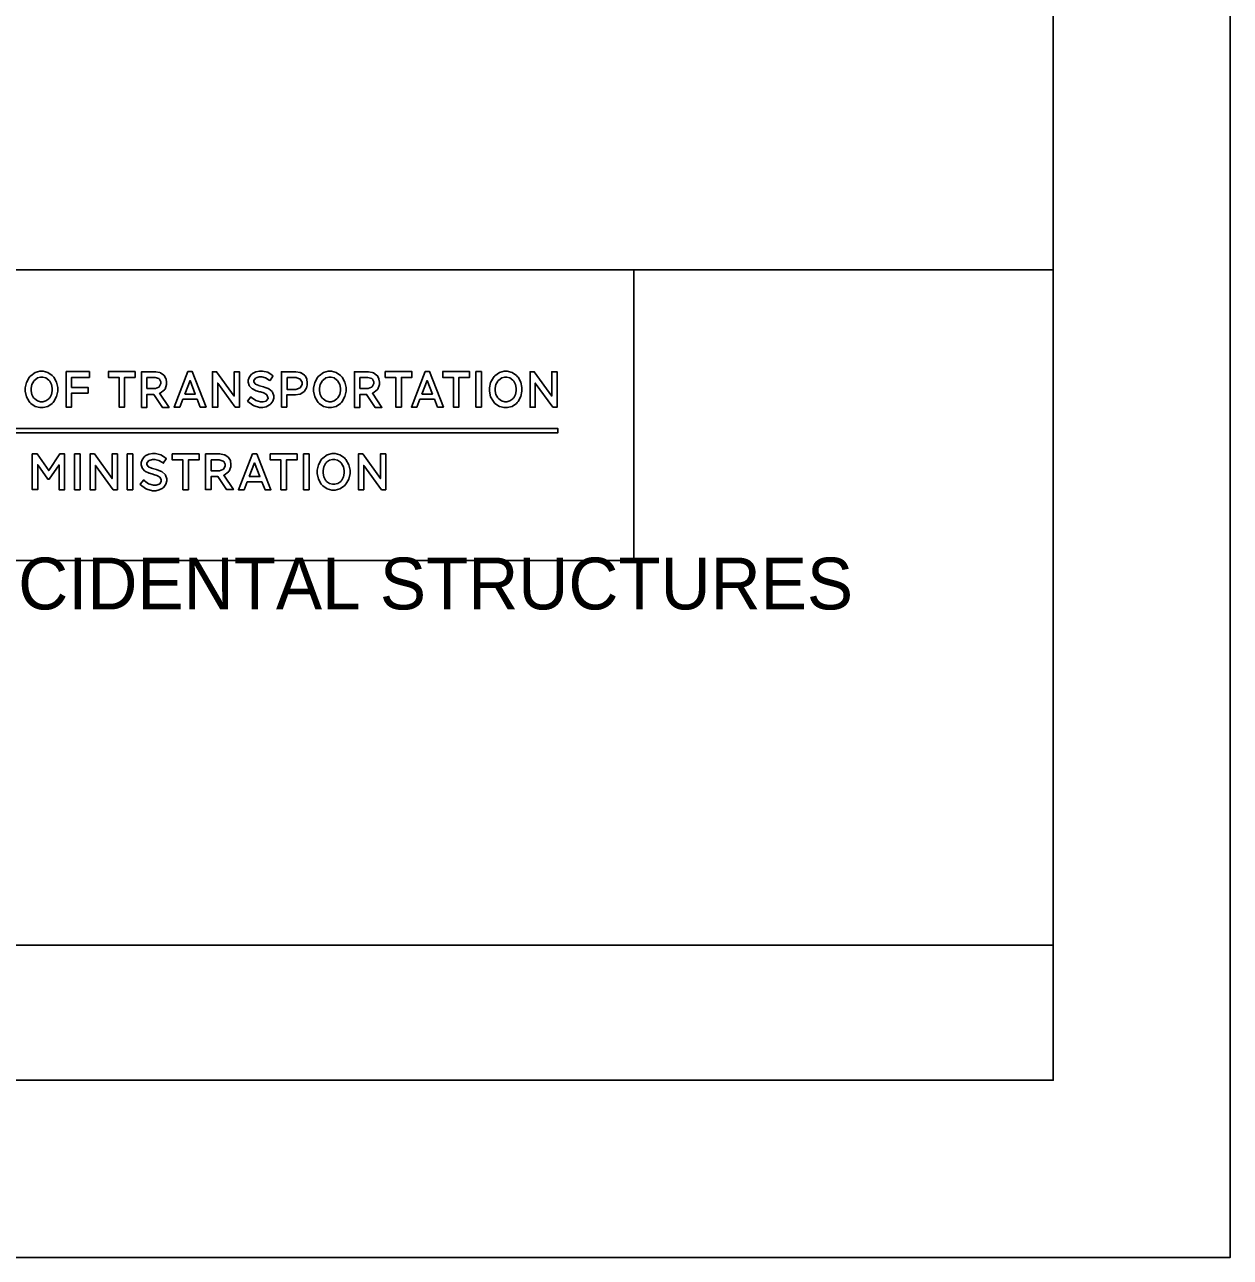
# Model space of a CAD drawing. Extents: x 12.2 to 54.5, y -7.8 to 16.1.
# Drawn here: x 52.376 to 54.534, y -7.78 to -5.573 of the extents above; entities that cross this region are included whole.
import ezdxf

# ---------------------------------------------------------------- set-up
doc = ezdxf.new("R2010")
doc.units = 0
for name, color, linetype in [('BORD-LINE', 7, 'Continuous'), ('MSHA-LOGO', 7, 'Continuous'), ('TTLB-TEXT', 7, 'Continuous'), ('USER-BORD', 7, 'Continuous'), ('USER-LINE', 7, 'Continuous')]:
    doc.layers.add(name, color=color, linetype=linetype)

msp = doc.modelspace()

# ---------------------------------------------------------------- linework, layer by layer
at = {"layer": 'BORD-LINE'}
for p, q in [((54.2173, -6.0121), (49.7444, -6.0121)), ((49.7444, -7.2211), (54.2173, -7.2211))]:
    msp.add_line(p, q, dxfattribs=at)
msp.add_lwpolyline([(46.8431, 2.8902), (54.2173, 2.8902), (54.2173, -7.4629), (46.8431, -7.4629)], close=True, dxfattribs=at)
at = {"layer": 'MSHA-LOGO'}
for points in [[(52.3857, -6.2033), (52.3871, -6.2018), (52.395, -6.1962), (52.4035, -6.1938), (52.4063, -6.1938), (52.4091, -6.1938), (52.4176, -6.1961), (52.4255, -6.2014), (52.4269, -6.203), (52.4283, -6.2046), (52.4333, -6.2135), (52.4354, -6.2231), (52.4354, -6.2264), (52.4354, -6.2296), (52.4333, -6.2392), (52.4283, -6.2482), (52.4269, -6.2497), (52.4255, -6.2513), (52.4176, -6.2567), (52.4091, -6.2589), (52.4063, -6.2589), (52.4035, -6.2589), (52.395, -6.2567), (52.3871, -6.2513), (52.3857, -6.2497), (52.3843, -6.2482), (52.3793, -6.2393), (52.3772, -6.2296), (52.3772, -6.2264), (52.3772, -6.2232), (52.3793, -6.2137), (52.3843, -6.2049)], [(52.4502, -6.1945), (52.4921, -6.1945), (52.4921, -6.2047), (52.46, -6.2047), (52.46, -6.2228), (52.4898, -6.2228), (52.4898, -6.233), (52.46, -6.233), (52.46, -6.258), (52.4502, -6.258)], [(52.5258, -6.1945), (52.5739, -6.1945), (52.5739, -6.2047), (52.5549, -6.2047), (52.5549, -6.258), (52.5451, -6.258), (52.5451, -6.2047), (52.5261, -6.2047), (52.5261, -6.1945)], [(52.5853, -6.2583), (52.5853, -6.1948), (52.6076, -6.1948), (52.6104, -6.1948), (52.6179, -6.1962), (52.6187, -6.1964), (52.6194, -6.1967), (52.6252, -6.2006), (52.6256, -6.201), (52.626, -6.2015), (52.6289, -6.2067), (52.6292, -6.2073), (52.6294, -6.2079), (52.6302, -6.2131), (52.6302, -6.2149), (52.6302, -6.2177), (52.6274, -6.2256), (52.6269, -6.2264), (52.6263, -6.2272), (52.6187, -6.233), (52.6177, -6.2333), (52.6347, -6.2586), (52.6226, -6.2586), (52.6072, -6.2353), (52.5951, -6.2353), (52.5951, -6.2586), (52.5853, -6.2586)], [(52.6685, -6.1945), (52.676, -6.1945), (52.7008, -6.258), (52.6904, -6.258), (52.6848, -6.2438), (52.6593, -6.2438), (52.6537, -6.258), (52.6436, -6.258)], [(52.7532, -6.2583), (52.7218, -6.2149), (52.7218, -6.2583), (52.7123, -6.2583), (52.7123, -6.1948), (52.7198, -6.1948), (52.7512, -6.2382), (52.7512, -6.1948), (52.7607, -6.1948), (52.7607, -6.2583)], [(52.8095, -6.2359), (52.8092, -6.2356), (52.8051, -6.2329), (52.8046, -6.2326), (52.8041, -6.2325), (52.7984, -6.2308), (52.7977, -6.2307), (52.7971, -6.2305), (52.7908, -6.2286), (52.7902, -6.2284), (52.7895, -6.2281), (52.7838, -6.2254), (52.7833, -6.2251), (52.7828, -6.2247), (52.7787, -6.2204), (52.7784, -6.2198), (52.7781, -6.2192), (52.7765, -6.2135), (52.7765, -6.2116), (52.7765, -6.2098), (52.7779, -6.2047), (52.7816, -6.1996), (52.7827, -6.1988), (52.7837, -6.1978), (52.7898, -6.1947), (52.7965, -6.1935), (52.7987, -6.1935), (52.8018, -6.1935), (52.8112, -6.1957), (52.8193, -6.2011), (52.8206, -6.2027), (52.8154, -6.2106), (52.8141, -6.2095), (52.8075, -6.2057), (52.8006, -6.204), (52.7984, -6.204), (52.7962, -6.204), (52.7904, -6.2056), (52.7899, -6.206), (52.7893, -6.2063), (52.7866, -6.2103), (52.7866, -6.2116), (52.7866, -6.2128), (52.7888, -6.2162), (52.7892, -6.2165), (52.7896, -6.2168), (52.7951, -6.2193), (52.7957, -6.2195), (52.7964, -6.2196), (52.8035, -6.2215), (52.8043, -6.2218), (52.805, -6.222), (52.8121, -6.2247), (52.8128, -6.2251), (52.8134, -6.2254), (52.8189, -6.23), (52.8193, -6.2307), (52.8197, -6.2313), (52.8219, -6.2377), (52.8219, -6.2399), (52.8219, -6.2417), (52.8204, -6.2473), (52.8168, -6.2524), (52.8157, -6.2534), (52.8146, -6.2542), (52.8086, -6.2573), (52.8024, -6.2586), (52.8003, -6.2586), (52.7967, -6.2586), (52.7871, -6.2559), (52.7859, -6.2553), (52.7848, -6.2547), (52.7758, -6.2479), (52.7751, -6.2471), (52.781, -6.2395), (52.7823, -6.241), (52.7899, -6.2464), (52.7982, -6.2488), (52.801, -6.2488), (52.803, -6.2488), (52.8084, -6.2471), (52.8088, -6.2468), (52.8093, -6.2464), (52.8118, -6.2425), (52.8118, -6.2412), (52.8117, -6.2406), (52.8098, -6.2362)], [(52.8357, -6.2583), (52.8357, -6.1948), (52.8586, -6.1948), (52.8615, -6.1948), (52.8695, -6.1962), (52.8704, -6.1964), (52.8712, -6.1968), (52.8771, -6.2009), (52.8776, -6.2014), (52.878, -6.2019), (52.881, -6.2074), (52.8812, -6.208), (52.8813, -6.2085), (52.8821, -6.2138), (52.8821, -6.2155), (52.8821, -6.2174), (52.8811, -6.2225), (52.8808, -6.2231), (52.8806, -6.2236), (52.8773, -6.2292), (52.8769, -6.2297), (52.8765, -6.2302), (52.8702, -6.2343), (52.8694, -6.2346), (52.8686, -6.2349), (52.8608, -6.2362), (52.8583, -6.2362), (52.8452, -6.2362), (52.8452, -6.258), (52.8357, -6.258)], [(52.9018, -6.2033), (52.9032, -6.2018), (52.9111, -6.1962), (52.9196, -6.1938), (52.9224, -6.1938), (52.9252, -6.1938), (52.9337, -6.1961), (52.9416, -6.2014), (52.943, -6.203), (52.9444, -6.2046), (52.9493, -6.2135), (52.9515, -6.2231), (52.9515, -6.2264), (52.9515, -6.2296), (52.9493, -6.2392), (52.9444, -6.2482), (52.943, -6.2497), (52.9416, -6.2513), (52.9337, -6.2567), (52.9252, -6.2589), (52.9224, -6.2589), (52.9196, -6.2589), (52.9111, -6.2567), (52.9032, -6.2513), (52.9018, -6.2497), (52.9004, -6.2482), (52.8954, -6.2393), (52.8933, -6.2296), (52.8933, -6.2264), (52.8933, -6.2241), (52.8956, -6.2137), (52.9004, -6.2049)], [(52.9663, -6.2583), (52.9663, -6.1948), (52.9885, -6.1948), (52.9913, -6.1948), (52.9988, -6.1962), (52.9996, -6.1964), (53.0004, -6.1967), (53.0061, -6.2006), (53.0065, -6.201), (53.0069, -6.2015), (53.0098, -6.2067), (53.0101, -6.2073), (53.0102, -6.2079), (53.0111, -6.2131), (53.0111, -6.2149), (53.0111, -6.2177), (53.0084, -6.2256), (53.0078, -6.2264), (53.0072, -6.2272), (52.9996, -6.233), (52.9986, -6.2333), (53.0157, -6.2586), (53.0035, -6.2586), (52.9882, -6.2353), (52.9761, -6.2353), (52.9761, -6.2586), (52.9663, -6.2586)], [(53.0212, -6.1945), (53.0693, -6.1945), (53.0693, -6.2047), (53.0504, -6.2047), (53.0504, -6.258), (53.0405, -6.258), (53.0405, -6.2047), (53.0215, -6.2047), (53.0215, -6.1945)], [(53.0932, -6.1945), (53.1008, -6.1945), (53.1256, -6.258), (53.1152, -6.258), (53.1096, -6.2438), (53.0837, -6.2438), (53.0782, -6.258), (53.0684, -6.258)], [(53.1243, -6.1945), (53.1724, -6.1945), (53.1724, -6.2047), (53.1534, -6.2047), (53.1534, -6.258), (53.1436, -6.258), (53.1436, -6.2047), (53.1246, -6.2047), (53.1246, -6.1945)], [(53.1839, -6.1945), (53.1937, -6.1945), (53.1937, -6.258), (53.1839, -6.258)], [(53.2166, -6.2033), (53.218, -6.2018), (53.2259, -6.1962), (53.2344, -6.1938), (53.2372, -6.1938), (53.24, -6.1938), (53.2485, -6.1961), (53.2564, -6.2014), (53.2578, -6.203), (53.2592, -6.2046), (53.2642, -6.2135), (53.2663, -6.2231), (53.2663, -6.2264), (53.2663, -6.2296), (53.2642, -6.2392), (53.2592, -6.2482), (53.2578, -6.2497), (53.2564, -6.2513), (53.2485, -6.2567), (53.24, -6.2589), (53.2372, -6.2589), (53.2344, -6.2589), (53.2259, -6.2567), (53.218, -6.2513), (53.2166, -6.2497), (53.2152, -6.2482), (53.2102, -6.2393), (53.2081, -6.2296), (53.2081, -6.2264), (53.2081, -6.2232), (53.2101, -6.2137), (53.2151, -6.2049)], [(53.3216, -6.2583), (53.2902, -6.2149), (53.2902, -6.2583), (53.2807, -6.2583), (53.2807, -6.1948), (53.2883, -6.1948), (53.3197, -6.2382), (53.3197, -6.1948), (53.3292, -6.1948), (53.3292, -6.2583)], [(52.3932, -6.2422), (52.3941, -6.2432), (52.3993, -6.2469), (52.4048, -6.2484), (52.4067, -6.2484), (52.4085, -6.2484), (52.414, -6.2469), (52.4192, -6.2432), (52.4201, -6.2422), (52.421, -6.2412), (52.4242, -6.2352), (52.4256, -6.2286), (52.4256, -6.2264), (52.4256, -6.2241), (52.4242, -6.2175), (52.421, -6.2116), (52.4201, -6.2106), (52.4192, -6.2095), (52.414, -6.2058), (52.4085, -6.2043), (52.4067, -6.2043), (52.4048, -6.2043), (52.3993, -6.2058), (52.3941, -6.2095), (52.3932, -6.2106), (52.3923, -6.2116), (52.3891, -6.2175), (52.3877, -6.2241), (52.3877, -6.2264), (52.3877, -6.2286), (52.389, -6.2352), (52.3922, -6.2412)], [(52.5951, -6.205), (52.5951, -6.2244), (52.6079, -6.2244), (52.6101, -6.2244), (52.6162, -6.2222), (52.6167, -6.2218), (52.6172, -6.2214), (52.62, -6.216), (52.62, -6.2142), (52.62, -6.2125), (52.6175, -6.2077), (52.6171, -6.2073), (52.6166, -6.2069), (52.6098, -6.205), (52.6076, -6.205)], [(52.6629, -6.2346), (52.6815, -6.2346), (52.6721, -6.2106)], [(52.8458, -6.205), (52.8458, -6.2264), (52.8589, -6.2264), (52.8615, -6.2264), (52.8692, -6.2236), (52.8726, -6.2175), (52.8726, -6.2155), (52.8726, -6.2136), (52.8694, -6.2077), (52.862, -6.205), (52.8596, -6.205)], [(52.9093, -6.2422), (52.9102, -6.2432), (52.9154, -6.2469), (52.9209, -6.2484), (52.9227, -6.2484), (52.9245, -6.2484), (52.93, -6.2469), (52.9352, -6.2432), (52.9361, -6.2422), (52.937, -6.2412), (52.9403, -6.2352), (52.9417, -6.2286), (52.9417, -6.2264), (52.9417, -6.2241), (52.9403, -6.2175), (52.937, -6.2116), (52.9361, -6.2106), (52.9352, -6.2095), (52.93, -6.2058), (52.9245, -6.2043), (52.9227, -6.2043), (52.9209, -6.2043), (52.9155, -6.2058), (52.9103, -6.2095), (52.9093, -6.2106), (52.9084, -6.2116), (52.9052, -6.2175), (52.9037, -6.2241), (52.9037, -6.2264), (52.9037, -6.2286), (52.905, -6.2352), (52.9083, -6.2412)], [(52.9761, -6.205), (52.9761, -6.2244), (52.9888, -6.2244), (52.991, -6.2244), (52.9971, -6.2222), (52.9977, -6.2218), (52.9981, -6.2214), (53.0009, -6.216), (53.0009, -6.2142), (53.0009, -6.2125), (52.9985, -6.2077), (52.998, -6.2073), (52.9975, -6.2069), (52.9907, -6.205), (52.9885, -6.205)], [(53.0873, -6.2346), (53.106, -6.2346), (53.0965, -6.2106)], [(53.2238, -6.2422), (53.2247, -6.2432), (53.2299, -6.2469), (53.2354, -6.2484), (53.2372, -6.2484), (53.239, -6.2484), (53.2445, -6.2469), (53.2497, -6.2432), (53.2506, -6.2422), (53.2515, -6.2412), (53.2548, -6.2352), (53.2562, -6.2286), (53.2562, -6.2264), (53.2562, -6.2241), (53.2548, -6.2175), (53.2515, -6.2116), (53.2506, -6.2106), (53.2497, -6.2095), (53.2445, -6.2058), (53.239, -6.2043), (53.2372, -6.2043), (53.2354, -6.2043), (53.23, -6.2058), (53.2248, -6.2095), (53.2238, -6.2106), (53.2229, -6.2116), (53.2197, -6.2175), (53.2182, -6.2241), (53.2182, -6.2264), (53.2182, -6.2286), (53.2197, -6.2352), (53.2229, -6.2412)], [(51.2136, -6.2962), (53.3302, -6.2962), (53.3302, -6.3041), (51.2136, -6.3041)], [(52.3898, -6.3418), (52.3987, -6.3418), (52.4192, -6.3716), (52.439, -6.3418), (52.4476, -6.3418), (52.4476, -6.406), (52.4377, -6.406), (52.4377, -6.3614), (52.4201, -6.3867), (52.4176, -6.3867), (52.3997, -6.361), (52.3997, -6.4057), (52.3898, -6.4057)], [(52.4655, -6.3418), (52.4754, -6.3418), (52.4754, -6.406), (52.4655, -6.406)], [(52.5345, -6.406), (52.5029, -6.3623), (52.5029, -6.406), (52.4933, -6.406), (52.4933, -6.3418), (52.501, -6.3418), (52.5326, -6.3858), (52.5326, -6.3418), (52.5422, -6.3418), (52.5422, -6.406)], [(52.5597, -6.3418), (52.5696, -6.3418), (52.5696, -6.406), (52.5597, -6.406)], [(52.6185, -6.3838), (52.6182, -6.3835), (52.614, -6.3809), (52.6134, -6.3806), (52.6129, -6.3805), (52.607, -6.3785), (52.6064, -6.3784), (52.6057, -6.3782), (52.5994, -6.3764), (52.5987, -6.3761), (52.5981, -6.3759), (52.5922, -6.3732), (52.5917, -6.3729), (52.5911, -6.3726), (52.5869, -6.368), (52.5866, -6.3675), (52.5863, -6.3669), (52.5847, -6.361), (52.5847, -6.3591), (52.5847, -6.3574), (52.5863, -6.3521), (52.59, -6.3471), (52.5911, -6.3463), (52.5921, -6.3454), (52.5982, -6.3424), (52.6051, -6.3411), (52.6074, -6.3411), (52.6105, -6.3411), (52.6201, -6.3435), (52.6284, -6.3489), (52.6297, -6.3504), (52.6243, -6.3585), (52.6231, -6.3573), (52.6164, -6.3534), (52.6094, -6.3517), (52.607, -6.3517), (52.6049, -6.3517), (52.599, -6.3533), (52.5984, -6.3537), (52.5978, -6.354), (52.5949, -6.3581), (52.5949, -6.3594), (52.5949, -6.3607), (52.5971, -6.3642), (52.5975, -6.3646), (52.5979, -6.3649), (52.6034, -6.3673), (52.6042, -6.3675), (52.6049, -6.3676), (52.612, -6.3698), (52.6128, -6.37), (52.6136, -6.3703), (52.6208, -6.373), (52.6214, -6.3732), (52.622, -6.3736), (52.6276, -6.3784), (52.6281, -6.379), (52.6285, -6.3797), (52.6307, -6.3862), (52.6307, -6.3883), (52.6307, -6.3902), (52.629, -6.396), (52.6253, -6.4013), (52.6243, -6.4021), (52.6232, -6.403), (52.6172, -6.4062), (52.6108, -6.4076), (52.6086, -6.4076), (52.605, -6.4076), (52.5951, -6.4049), (52.5939, -6.4044), (52.5927, -6.4038), (52.5837, -6.3968), (52.5831, -6.396), (52.5892, -6.3883), (52.5904, -6.3899), (52.598, -6.3953), (52.6067, -6.3976), (52.6096, -6.3976), (52.6116, -6.3976), (52.6171, -6.396), (52.6176, -6.3957), (52.6181, -6.3954), (52.6205, -6.3913), (52.6205, -6.3899), (52.6205, -6.3884), (52.6189, -6.3842)], [(52.6399, -6.3418), (52.6885, -6.3418), (52.6885, -6.3524), (52.6693, -6.3524), (52.6693, -6.406), (52.6594, -6.406), (52.6594, -6.3524), (52.6403, -6.3524), (52.6403, -6.3418)], [(52.7, -6.406), (52.7, -6.3418), (52.7227, -6.3418), (52.7255, -6.3418), (52.7331, -6.3431), (52.7339, -6.3434), (52.7347, -6.3436), (52.7405, -6.3474), (52.7409, -6.3479), (52.7413, -6.3484), (52.7443, -6.3537), (52.7444, -6.3543), (52.7446, -6.3548), (52.7454, -6.36), (52.7454, -6.3617), (52.7454, -6.3646), (52.7424, -6.3724), (52.7419, -6.3732), (52.7413, -6.374), (52.7335, -6.3797), (52.7326, -6.38), (52.7499, -6.4057), (52.7377, -6.4057), (52.7221, -6.3822), (52.7099, -6.3822), (52.7099, -6.4057), (52.7, -6.4057)], [(52.7099, -6.3524), (52.7099, -6.372), (52.7227, -6.372), (52.7249, -6.372), (52.7311, -6.3698), (52.7316, -6.3694), (52.7322, -6.3689), (52.7348, -6.3637), (52.7348, -6.362), (52.7348, -6.3602), (52.7324, -6.3553), (52.732, -6.3549), (52.7315, -6.3545), (52.7246, -6.3524), (52.7224, -6.3524)], [(52.7841, -6.3418), (52.7917, -6.3418), (52.8169, -6.406), (52.8064, -6.406), (52.8007, -6.3919), (52.7745, -6.3919), (52.769, -6.406), (52.7588, -6.406)], [(52.8154, -6.3418), (52.8639, -6.3418), (52.8639, -6.3524), (52.8448, -6.3524), (52.8448, -6.406), (52.8348, -6.406), (52.8348, -6.3524), (52.8157, -6.3524), (52.8157, -6.3418)], [(52.8754, -6.3418), (52.8853, -6.3418), (52.8853, -6.406), (52.8754, -6.406)], [(52.9083, -6.3508), (52.9098, -6.3492), (52.9179, -6.3435), (52.9263, -6.3411), (52.9291, -6.3411), (52.9319, -6.3411), (52.9404, -6.3435), (52.9485, -6.3489), (52.9499, -6.3504), (52.9512, -6.352), (52.9562, -6.361), (52.9585, -6.3706), (52.9585, -6.3739), (52.9585, -6.3771), (52.9563, -6.3867), (52.9513, -6.3957), (52.9499, -6.3973), (52.9484, -6.3989), (52.9403, -6.4044), (52.9319, -6.4066), (52.9291, -6.4066), (52.9262, -6.4066), (52.9176, -6.4043), (52.9097, -6.3988), (52.9083, -6.3973), (52.9069, -6.3958), (52.9019, -6.3868), (52.8997, -6.3771), (52.8997, -6.3739), (52.8997, -6.3707), (52.9019, -6.3612), (52.9069, -6.3523)], [(52.9157, -6.3899), (52.9166, -6.391), (52.9219, -6.3945), (52.9273, -6.396), (52.9291, -6.396), (52.931, -6.396), (52.9366, -6.3945), (52.9419, -6.391), (52.9428, -6.3899), (52.9438, -6.3889), (52.947, -6.3829), (52.9483, -6.3761), (52.9483, -6.3739), (52.9483, -6.3717), (52.9468, -6.365), (52.9435, -6.3589), (52.9425, -6.3578), (52.9416, -6.3568), (52.9363, -6.3532), (52.9309, -6.3517), (52.9291, -6.3517), (52.9273, -6.3517), (52.9218, -6.3532), (52.9165, -6.3568), (52.9157, -6.3578), (52.9148, -6.3589), (52.9116, -6.3649), (52.9103, -6.3716), (52.9103, -6.3739), (52.9103, -6.3761), (52.9116, -6.3829), (52.9148, -6.3889)], [(53.0147, -6.406), (52.9831, -6.3623), (52.9831, -6.406), (52.9735, -6.406), (52.9735, -6.3418), (52.9812, -6.3418), (53.0128, -6.3858), (53.0128, -6.3418), (53.0224, -6.3418), (53.0224, -6.406)], [(52.7783, -6.3822), (52.7971, -6.3822), (52.7876, -6.3578)]]:
    msp.add_lwpolyline(points, close=True, dxfattribs=at)
at = {"layer": 'TTLB-TEXT'}
msp.add_line((54.2173, -7.4629), (54.2173, -7.4629), dxfattribs=at)
at = {"layer": 'USER-BORD'}
msp.add_lwpolyline([(54.5342, 3.2202), (46.0342, 3.2202), (46.0342, -7.7798), (54.5342, -7.7798)], close=True, dxfattribs=at)
at = {"layer": 'USER-LINE'}
msp.add_lwpolyline([(53.4665, -6.5328), (50.4953, -6.5328), (50.4953, -6.0121), (53.4665, -6.0121)], close=True, dxfattribs=at)

# ---------------------------------------------------------------- texts
at = {"layer": 'BORD-LINE'}
msp.add_text('HDVBARREIRA', height=6e-12, rotation=180, dxfattribs=at).set_placement((54.2173, -6.0121))
at = {"layer": 'TTLB-TEXT'}
msp.add_text('STANDARDS FOR HIGHWAYS AND INCIDENTAL STRUCTURES', height=0.09269, rotation=360, dxfattribs=at).set_placement((50.1402, -6.6201))

doc.saveas('drawing.dxf')
